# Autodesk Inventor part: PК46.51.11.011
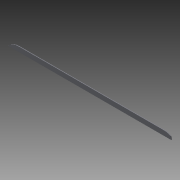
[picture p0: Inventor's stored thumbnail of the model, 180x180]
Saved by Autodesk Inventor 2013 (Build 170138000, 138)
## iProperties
Shininess: 64.0
Length Units: 11269
Angle Units: 11279
Time Units: 11290
Mass Units: 11283
Length Display Precision: 3
Angle Display Precision: 2
Compacted: True
Part Number: PК46.51.11.011
Document SubType Name: Листовой материал
Created: 2004-12
Material: Steel, Mild
Designer: =<Author>
Manufacturer: Standard
Standards Organization: Custom
Description: strip seal
Density: 7.86 g/cm^3
Sheet Metal Rule: По умолчанию
Mass: 117.099 g
Surface Area: 169.669 cm^2
Volume: 14.8981 cm^3
Density: 0.0
Volumn: 0.0
Area: 0.0
PropertySet Name: Model Information
Control State: 0
Master: False
Checked Out: False
Checked Out Date: 2008-10-15
Last Check In Date: 2008-10-15
Author: PVitaliy
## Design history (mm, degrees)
node "ФлнОтгиб1"
feature "Вырез1" dims "d10" = 2 (= Толщина), "d11" = 0
feature "Вырез2" dims "d14" = 2 (= Толщина), "d15" = 0
feature "Вырез3" dims "d17" = 2 (= Толщина), "d18" = 0
body "Solid1"
sketch "Эскиз1"
  geometry: L1 (0, 0)-(522, 0)
  constraints: 2 end point, 1 horizontal, 1 other
  dimensions: "d0" = 522 distance of L1.start L1.end
feature "Пластина1" dims "d2" = 15, "d3" = 2 (= Ширина_просечки), "d5" = 4 (= Минимальный_остаток), "d7" = 2 (= Радиус_гибки), "d8" = 2, "Толщина" = 2
feature "Изгиб1" dims "d3" = 2 (= Ширина_просечки), "d4" = 1 (= Глубина_просечки), "d5" = 4 (= Минимальный_остаток), "d6" = 2 (= Радиус_гибки), "d7" = 2 (= Радиус_гибки), "d8" = 2, "Толщина" = 2, "Зазор_стыка" = 0.01
sketch "Эскиз2"
  geometry: L1 (0, -15)-(522, -15) reference; L2 (522, 0)-(522, -15) reference; L3 (522, 0)-(519.355, -15)
  constraints: 2 end point, 1 point on line
  dimensions: "d9" = 10 deg angle of L2 L3
sketch "Эскиз3"
  geometry: L1 (519.355, 0)-(522, 15) reference; L2 (0, 0)-(519.355, 0) reference; A1 r 45 centre (499, 45) between (499, 0) and (520.3, 5.36)
  constraints: 2 point on circle, 2 point on line, 1 centre point, 1 tangent
  dimensions: "d12" = 90 diameter of A1; "d13" = 23 horizontal distance of A1.centre L1.end
sketch "Эскиз4"
  geometry: L1 (0, 15)-(522, 15) reference; L2 (0, 15)-(0, 0) reference; L3 (0, 0)-(499, 0) reference; A1 r 45 centre (45, 45) between (11.459, 15) and (45, 0)
  constraints: 2 point on circle, 2 point on line, 2 tangent, 1 centre point
  dimensions: "d16" = 90 diameter of A1
other parameters: "Радиус_гибки" = 2 (= Толщина), "Ширина_просечки" = 2 (= Толщина), "Глубина_просечки" = 1 (= 0.5 x Толщина), "Размер_высечки" = 8 (= 4 x Толщина), "Минимальный_остаток" = 4 (= 2 x Толщина), "Радиус_перехода" = 2 (= Радиус_гибки), "JacobiRadiusSize" = 2 (= Толщина), "GapSize" = 2 (= Толщина)
